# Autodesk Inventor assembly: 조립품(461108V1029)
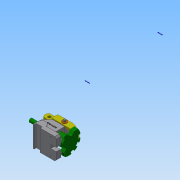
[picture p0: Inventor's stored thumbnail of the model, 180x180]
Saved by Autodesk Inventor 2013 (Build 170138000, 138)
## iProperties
Created: 2016-11
Part Number: 조립품(461108V1029)
Document SubType Name: Assembly
Designer: Administrator
Author: Administrator
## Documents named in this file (8)
- C:\Users\Administrator\Desktop\461108V1029\조립품(461108V1029).iam
- C:\Users\Administrator\Desktop\461108V1029\본체.ipt
- C:\Users\Administrator\Desktop\461108V1029\부시.ipt
- C:\Users\Administrator\Desktop\461108V1029\분할대.ipt
- C:\Users\Administrator\Desktop\461108V1029\분할축.ipt
- C:\Users\Administrator\Desktop\461108V1029\와셔.ipt
- C:\Users\Administrator\Desktop\461108V1029\원통형핀.ipt
- C:\Users\Administrator\Desktop\461108V1029\클레비스핀.ipt
